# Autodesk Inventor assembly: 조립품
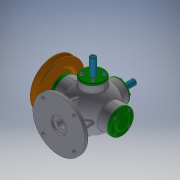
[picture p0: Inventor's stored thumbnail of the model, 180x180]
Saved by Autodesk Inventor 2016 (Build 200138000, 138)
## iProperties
Created: 2019-11
Part Number: 조립품
Material: 일반
Document SubType Name: Assembly
Designer: user
Author: user
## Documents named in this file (17)
- C:\Users\user\Desktop\391120V1007\조립품.iam
- C:\Users\user\Desktop\391120V1007\V-벨트풀리.ipt
- C:\Users\user\Desktop\391120V1007\가변스프링.ipt
- C:\Users\user\Desktop\391120V1007\가변스프링2.ipt
- C:\Users\user\Desktop\391120V1007\너트 M8x1.ipt
- C:\Users\user\Desktop\391120V1007\뒤커버.ipt
- C:\Users\user\Desktop\391120V1007\베어링 6202.ipt
- C:\Users\user\Desktop\391120V1007\본체.ipt
- C:\Users\user\Desktop\391120V1007\본체커버.ipt
- C:\Users\user\Desktop\391120V1007\볼트 M4.ipt
- C:\Users\user\Desktop\391120V1007\슬라이드 커버.ipt
- C:\Users\user\Desktop\391120V1007\슬라이드.ipt
- C:\Users\user\Desktop\391120V1007\앞커버.ipt
- C:\Users\user\Desktop\391120V1007\오일 실.ipt
- C:\Users\user\Desktop\391120V1007\와셔 8x17.ipt
- C:\Users\user\Desktop\391120V1007\축.ipt
- C:\Users\user\Desktop\391120V1007\키 4x4.ipt
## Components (3 placed, 3 different names)
1. V-벨트풀리:1 — 플러쉬:2
2. 가변스프링:1
3. 가변스프링2:1
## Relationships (1: Flush 1)
- 플러쉬:2 [Flush]: V-벨트풀리:1
